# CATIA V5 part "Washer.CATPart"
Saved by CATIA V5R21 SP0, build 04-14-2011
Part number: washer
Bounding box of the stored display mesh (mm): x -24 to 24, y -23.825 to 23.825, z 0 to 3
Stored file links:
  D:\CATIA V5R21 E-RESOURCES\CATIA-V5R21\catia-v5r21-Prts\c12_catia_v5r21_prt\c12_catia_v5r21figr_12-49\Washer.CATPart
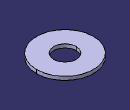
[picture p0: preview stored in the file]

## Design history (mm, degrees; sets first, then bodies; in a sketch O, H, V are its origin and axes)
Body1 (main body)
  Sketch1 on xy-plane, origin (0, 0, 0), H (1, 0, 0), V (0, 1, 0)
    circle A1 centre (0, 0) radius 24
    circle A2 centre (0, 0) radius 9.5
    radius A1 = 24
    radius A2 = 9.5
  Pad1: profile Sketch1, direction (0, 0, 1), length 3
